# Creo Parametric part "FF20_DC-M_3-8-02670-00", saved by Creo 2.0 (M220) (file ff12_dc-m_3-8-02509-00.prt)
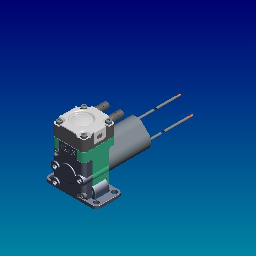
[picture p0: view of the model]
Units: millimeter Newton Second (mmNs); MM, TONNE, SECS

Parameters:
  PROI_CREATED_ON = "21.07.2008 11:36:02"
  PTC_WM_ITERATION = "13"
  PTC_WM_VERSION = "0.13"
  PTC_WM_LIFECYCLE_STATE = "in Bearbeitung"
  PTC_WM_LIFECYCLE = "KNF_EPMDocument"
  PTC_WM_LOCATION = "/Bibliotheken/Standard/Startmodels"
  PTC_WM_CREATED_BY = "Sven Fehrenbach (sfehrenbach: KNF)"
  PTC_WM_CREATED_ON = "15-Aug-08 02:26:31 PM"
  PTC_WM_MODIFIED_BY = "Produktmanager Flodos (pm1300: KNF)"
  PTC_WM_MODIFIED_ON = "30-Aug-16 08:35:49 AM"
  MATERIAL = "UNASSIGNED"
  PTC_MATERIAL_NAME = "UNASSIGNED"
  COPY_GEOM_ORIGIN_TYPE = "Part"

Other parameters: GEWICHT, VOLUMEN

Created from: KNF_STD_PART_SOLID.PRT

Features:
  1. coordinate system
  2. datum plane "RIGHT"
  3. datum plane "TOP"
  4. datum plane "FRONT"
  5. datum axis
  6. datum axis
  7. datum axis
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
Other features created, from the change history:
  planar section "A"
  planar section "B"
  planar section "C"
  patch "Verbundvolumen 1"

Other named items: A_X, A_Y, A_Z

Layers: AXIS-ACHSEN, CONSTR_ELEM-KONSTR_ELEM, GEOM_ELEMENT-GEOM_ELEMENT, MASSE, NOT_GEOM_ELEM-NICHT_GEOM_ELEM, PARAMETERDIM-PARAMETERBEM, PLANES-EBENEN, STANDARD-STANDARD, STD_AXIS-STD_ACHSEN, STD_COORD-STD_KOORDS, STD_PLANES-STD_EBENEN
